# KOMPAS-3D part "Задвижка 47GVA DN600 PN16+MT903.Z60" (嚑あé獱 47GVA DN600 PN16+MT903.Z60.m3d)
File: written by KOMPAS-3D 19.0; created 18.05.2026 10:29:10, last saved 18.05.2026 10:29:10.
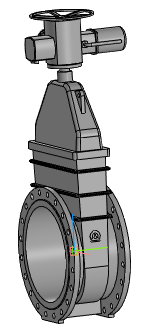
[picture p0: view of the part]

Document properties: Автор: Энергия; Полное имя файла: ..\Задвижка 47GVA DN50_DN1000+MT903.Z\Задвижка 47GVA DN600 PN16+MT903.Z60.a3d

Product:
- Part/product: Задвижка 47GVA DN600 PN16+MT903.Z60
    Масса: 1122.47
  - Body: Электропривод MT903.Z45-60
      Масса: 170.293
  - Body: Задвижка 47GVA DN600 PN16 без исполнительного механизма
      Масса: 952.177

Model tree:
1. Операция без истории:1
2. Операция без истории:2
